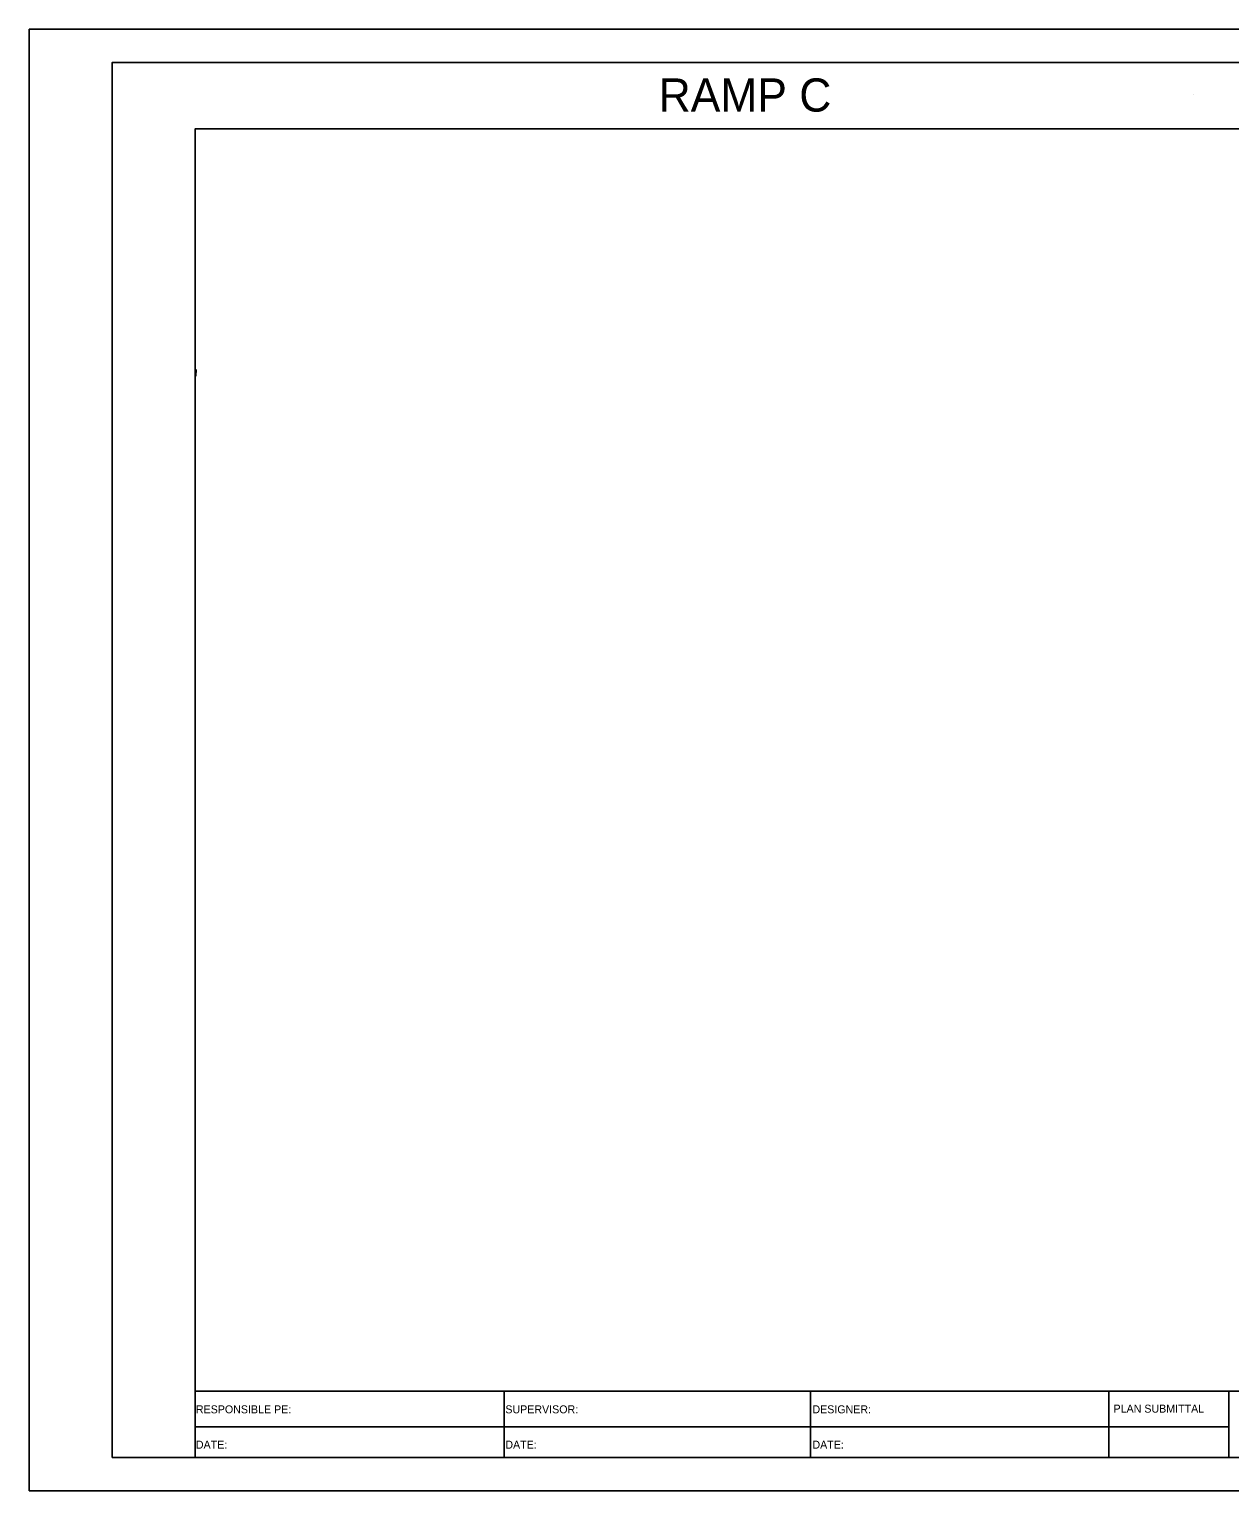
# Model space of a CAD drawing. Extents: x 1802116 to 1804496, y 250064 to 250284.
# Drawn here: x 1802116 to 1802296.8, y 250064.4 to 250284.4 of the extents above; entities that cross this region are included whole.
import ezdxf

# ---------------------------------------------------------------- set-up
doc = ezdxf.new("R2010")
doc.units = 0
for name, color, linetype in [('2', 7, 'Continuous'), ('ANNO-SHT', 7, 'Continuous'), ('ANNO-TXT', 7, 'Continuous'), ('AXIS', 7, 'Continuous'), ('DRAINAGE', 7, 'Continuous'), ('Level 1', 7, 'Continuous'), ('Level 62', 7, 'Continuous'), ('SHT-BDR', 7, 'Continuous'), ('SHT-BNDRY', 7, 'Continuous')]:
    doc.layers.add(name, color=color, linetype=linetype)

# ---------------------------------------------------------------- blocks, each defined once
blk = doc.blocks.new('SC47208')
at = {"layer": 'Level 1'}
blk.add_line((0, 0), (0, 0), dxfattribs=at)

msp = doc.modelspace()

# ---------------------------------------------------------------- linework, layer by layer
at = {"layer": '2'}
msp.add_lwpolyline([(1802141.12, 250233.21), (1802141.1, 250232.21)], dxfattribs=at)
msp.add_lwpolyline([(1802141.12, 250233.21), (1802141.1, 250232.21)], dxfattribs=at)
at = {"layer": 'AXIS'}
msp.add_line((1802141, 250189.42), (1802141, 250189.43), dxfattribs=at)
at = {"layer": 'Level 62'}
msp.add_lwpolyline([(1802116, 250064.42), (1802456, 250064.42), (1802456, 250284.42), (1802116, 250284.42)], close=True, dxfattribs=at)
at = {"layer": 'SHT-BDR'}
msp.add_lwpolyline([(1802141, 250079.43), (1802441, 250079.43), (1802441, 250269.43), (1802141, 250269.43)], close=True, dxfattribs=at)
at = {"layer": 'SHT-BNDRY'}
for p, q in [((1802141, 250069.42), (1802141, 250079.43)), ((1802187.52, 250079.43), (1802187.52, 250069.42)), ((1802233.67, 250069.42), (1802233.67, 250079.43)), ((1802278.59, 250069.42), (1802278.59, 250079.43)), ((1802296.63, 250069.42), (1802296.63, 250079.43)), ((1802141, 250074.03), (1802296.63, 250074.03))]:
    msp.add_line(p, q, dxfattribs=at)
msp.add_lwpolyline([(1802128.5, 250069.42), (1802451, 250069.42), (1802451, 250279.42), (1802128.5, 250279.42)], close=True, dxfattribs=at)

# ---------------------------------------------------------------- block references
at = {"layer": 'DRAINAGE', "xscale": 0.2, "yscale": 0.20000000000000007, "rotation": -116.41666666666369}
msp.add_blockref('SC47208', (1802291.32, 250274.62), dxfattribs=at)
msp.add_blockref('SC47208', (1802291.32, 250274.62), dxfattribs=at)

# ---------------------------------------------------------------- texts
at = {"layer": 'ANNO-SHT'}
msp.add_text('                 RAMP C                 ', height=4.9995, rotation=360, dxfattribs=at).set_placement((1802179.21, 250272.02))
at = {"layer": 'ANNO-TXT'}
for s, p in [('RESPONSIBLE PE:', (1802141.1, 250076.08)), ('SUPERVISOR:', (1802187.7, 250076.08)), ('DESIGNER:', (1802233.94, 250076.08)), ('PLAN SUBMITTAL', (1802279.28, 250076.18)), ('DATE:', (1802141.1, 250070.76)), ('DATE:', (1802187.7, 250070.76)), ('DATE:', (1802233.94, 250070.76))]:
    msp.add_text(s, height=1.2, rotation=360, dxfattribs=at).set_placement(p)

doc.saveas('drawing.dxf')
